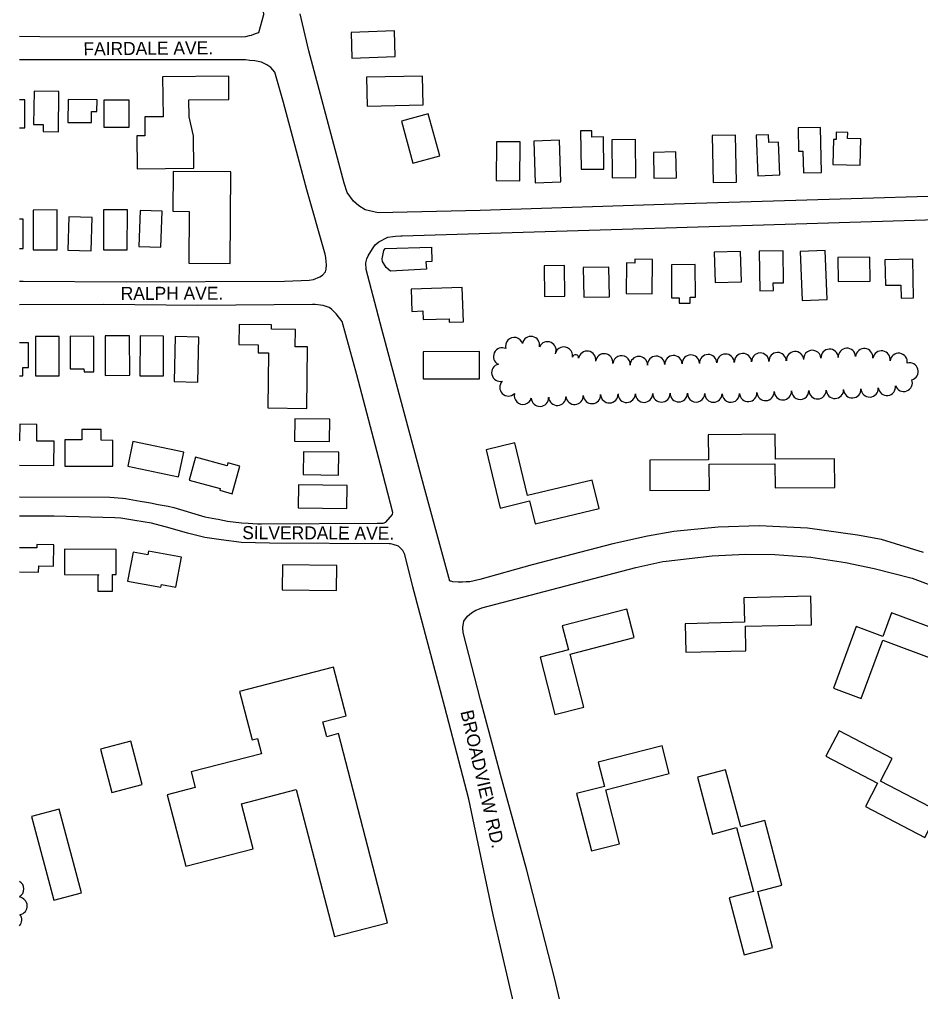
# Model space of a CAD drawing. Extents: x -25029 to 2274964, y -81170 to 687028.
# Drawn here: x -19748 to -18710, y -63741 to -62620 of the extents above; entities that cross this region are included whole.
import ezdxf

# ---------------------------------------------------------------- set-up
doc = ezdxf.new("R2010")
doc.units = 0
for name, color, linetype in [('BLDG', 7, 'Continuous'), ('ROAD', 7, 'Continuous'), ('ROAD-NAME', 7, 'Continuous'), ('TREES', 7, 'Continuous')]:
    doc.layers.add(name, color=color, linetype=linetype)

msp = doc.modelspace()

# ---------------------------------------------------------------- linework, layer by layer
at = {"layer": 'BLDG'}
for points in [[(-19366.4, -62635.5), (-19365.3, -62665.1), (-19315.4, -62663.3), (-19316.4, -62633.7)], [(-19604.1, -62732.9), (-19603.9, -62754.7), (-19613, -62754.8), (-19612.6, -62792.5), (-19547.3, -62791.8), (-19547.7, -62754.6), (-19552.9, -62732.7), (-19553.1, -62713.1), (-19507, -62712.6), (-19507.2, -62685.7), (-19583.4, -62686.5), (-19582.9, -62732.7)], [(-19283.2, -62718.8), (-19284, -62685.7), (-19348.5, -62687.2), (-19347.7, -62720.3)], [(-19732, -62741.6), (-19721, -62741.7), (-19721.1, -62749.8), (-19703.4, -62750), (-19703, -62703.4), (-19731.6, -62703.1)], [(-19692.5, -62739.2), (-19665.5, -62739.3), (-19665.4, -62726.6), (-19659.1, -62726.6), (-19659, -62713), (-19692.4, -62712.8)], [(-19651.1, -62744.7), (-19622.1, -62744.7), (-19622, -62713.6), (-19651, -62713.5)], [(-19308.4, -62737.8), (-19295.1, -62786.3), (-19264.1, -62777.7), (-19277.4, -62729.3)], [(-19075.7, -62755.9), (-19088.9, -62756.1), (-19089, -62748.7), (-19102, -62748.8), (-19101.4, -62793.2), (-19075.3, -62792.9)], [(-18851.3, -62745.6), (-18850.7, -62772.5), (-18845.8, -62772.4), (-18845.3, -62797.3), (-18824.5, -62796.9), (-18825.6, -62745.1)], [(-19126.2, -62759.8), (-19155.7, -62760.8), (-19154.2, -62808.7), (-19124.6, -62807.8)], [(-19065.4, -62803.1), (-19038.2, -62802.7), (-19038.7, -62758.8), (-19065.9, -62759.1)], [(-18923.5, -62753.7), (-18950.2, -62754.3), (-18949, -62808.5), (-18922.3, -62807.9)], [(-18874, -62761.8), (-18885, -62762.3), (-18885.4, -62753.4), (-18899.6, -62754), (-18897.6, -62800.7), (-18872.4, -62799.6)], [(-18778.9, -62758.2), (-18794.4, -62757.7), (-18794.2, -62750.8), (-18807.3, -62750.4), (-18807.5, -62758.8), (-18810.4, -62758.7), (-18811.3, -62787.5), (-18779.8, -62788.4)], [(-19171.6, -62761.7), (-19198.7, -62761.5), (-19199, -62806.3), (-19172, -62806.5)], [(-18992.1, -62773.2), (-19018, -62773.8), (-19017.4, -62803.5), (-18991.4, -62803)], [(-19571.4, -62795.6), (-19571.7, -62841.5), (-19552.9, -62841.7), (-19553.3, -62901.5), (-19505.7, -62901.9), (-19504.9, -62796.1)], [(-19705.1, -62840.1), (-19732.5, -62840.2), (-19732.4, -62886.1), (-19705.1, -62886)], [(-19692.6, -62886.3), (-19665.7, -62887.1), (-19664.5, -62848.9), (-19691.4, -62848.1)], [(-19651.7, -62886), (-19624.2, -62886.1), (-19623.9, -62840.1), (-19651.5, -62840)], [(-19610.9, -62882.1), (-19585.4, -62883), (-19584, -62841.6), (-19609.4, -62840.7)], [(-19279.6, -62908.4), (-19320.8, -62910.7), (-19325.9, -62906.4), (-19330.3, -62899.5), (-19330.5, -62896.4), (-19328.5, -62886.9), (-19327.2, -62884.5), (-19273.7, -62882.8), (-19273.3, -62899.4), (-19280.3, -62899.8)], [(-18946.9, -62923.7), (-18916.6, -62922.8), (-18917.6, -62887.9), (-18947.9, -62888.7)], [(-18895.5, -62933.1), (-18879.8, -62932.9), (-18879.9, -62924.2), (-18868, -62924.1), (-18868.5, -62887.3), (-18896.1, -62887.7)], [(-18846.8, -62944.3), (-18817.7, -62943.1), (-18820, -62886.7), (-18849.1, -62887.9)], [(-18805, -62922.6), (-18768.3, -62922.2), (-18768.7, -62894.3), (-18805.4, -62894.8)], [(-19120.6, -62904.2), (-19144, -62904.5), (-19143.5, -62939.7), (-19120.1, -62939.3)], [(-19069.5, -62905.9), (-19098.9, -62906.5), (-19098.2, -62940.7), (-19068.8, -62940.1)], [(-19019, -62897), (-19039.5, -62896.7), (-19039.5, -62901.3), (-19048.9, -62901.1), (-19049.4, -62936.2), (-19019.6, -62936.6)], [(-18997, -62941.5), (-18988.4, -62941.5), (-18988.4, -62947.5), (-18975.6, -62947.5), (-18975.6, -62940.5), (-18969.6, -62940.5), (-18969.8, -62903), (-18997.2, -62903.2)], [(-18750.8, -62926.9), (-18732.8, -62926.6), (-18732.5, -62941.6), (-18718.5, -62941.3), (-18719.3, -62896.8), (-18751.4, -62897.4)], [(-19297, -62931.2), (-19296.2, -62956.9), (-19283.8, -62956.5), (-19283.4, -62966.5), (-19253.4, -62965.6), (-19253.3, -62969.5), (-19236.9, -62969), (-19238.2, -62929.4)], [(-19417.3, -63068.8), (-19416.4, -62997.9), (-19430.7, -62997.7), (-19430.4, -62977.8), (-19458.1, -62977.4), (-19458, -62972.5), (-19495.1, -62972), (-19495.5, -62995.3), (-19473.2, -62995.6), (-19473.3, -63004.6), (-19461.3, -63004.7), (-19462.2, -63068.2)], [(-19621.3, -63030.5), (-19621.5, -62985.2), (-19649.8, -62985.3), (-19649.5, -63030.7)], [(-19582.3, -62985.4), (-19609.4, -62985.2), (-19609.6, -63031.1), (-19582.5, -63031.2)], [(-19730, -63031.2), (-19702.7, -63031.3), (-19702.6, -62985.8), (-19730, -62985.8)], [(-19689.9, -63023.2), (-19674.3, -63023.2), (-19673.7, -63026.6), (-19662.6, -63026.6), (-19662.5, -62985.8), (-19689.8, -62985.7)], [(-19570.3, -63037.8), (-19542.9, -63038.5), (-19541.7, -62986.5), (-19569.1, -62985.9)], [(-19283.2, -63034.6), (-19218.2, -63034.5), (-19218.3, -63003.2), (-19283.2, -63003.4)], [(-19431.6, -63106.6), (-19391.2, -63107.1), (-19390.9, -63081.1), (-19431.3, -63080.6)], [(-19640.6, -63105.6), (-19654.4, -63105.5), (-19654.4, -63093.1), (-19676.4, -63093), (-19676.5, -63105), (-19696, -63105), (-19696.1, -63135.2), (-19640.7, -63135.3)], [(-19623.6, -63135.4), (-19565.1, -63147.6), (-19559.1, -63119.1), (-19617.6, -63106.8)], [(-19088.6, -63151.4), (-19163, -63169.2), (-19177.5, -63108.5), (-19210.7, -63116.5), (-19194.6, -63183.6), (-19160.7, -63175.4), (-19154.3, -63201.9), (-19080.7, -63184.3)], [(-18809.4, -63126.7), (-18877.5, -63127.2), (-18877.7, -63098.6), (-18954.8, -63099.1), (-18954.5, -63128.1), (-19022.3, -63128.6), (-19022, -63163.4), (-18953.5, -63162.9), (-18953.7, -63133.2), (-18878.1, -63132.6), (-18877.9, -63160.4), (-18809.2, -63159.9)], [(-19421.5, -63145), (-19381, -63145.6), (-19380.6, -63119.3), (-19421.2, -63118.7)], [(-19552.8, -63151.3), (-19517.1, -63161.1), (-19517.7, -63163.1), (-19503.2, -63167.1), (-19494.4, -63135.2), (-19508.2, -63131.4), (-19509.1, -63134.8), (-19545.5, -63124.8)], [(-19427.1, -63183.3), (-19371.1, -63184.1), (-19370.7, -63157.8), (-19426.7, -63157)], [(-19658, -63260.8), (-19658.1, -63279.3), (-19641.1, -63279.4), (-19641, -63260), (-19637, -63260), (-19636.8, -63231.2), (-19696.3, -63230.9), (-19696.5, -63260.3), (-19657.1, -63260.6)], [(-19561.7, -63240.2), (-19599.7, -63233.2), (-19600.5, -63237.5), (-19617.5, -63234.4), (-19623.7, -63267.8), (-19585.3, -63274.9), (-19584.7, -63271.8), (-19568.1, -63274.9)], [(-19445.8, -63277.8), (-19383, -63278.6), (-19382.7, -63249.7), (-19445.4, -63248.9)], [(-18913.2, -63315.3), (-18981.5, -63317), (-18980.7, -63349.7), (-18911.4, -63348.1), (-18912.1, -63319.9), (-18836, -63318.1), (-18836.8, -63285.1), (-18913.8, -63287)], [(-19115.9, -63346.9), (-19148.6, -63355.3), (-19131.4, -63421.7), (-19098.2, -63413.1), (-19114, -63351.9), (-19040.3, -63332.9), (-19048.7, -63300.3), (-19123, -63319.5)], [(-18753.9, -63331.5), (-18784.3, -63320.2), (-18810.7, -63391.3), (-18778.6, -63403.2), (-18753.7, -63336), (-18691.2, -63359.2), (-18679.7, -63328.1), (-18743.8, -63304.3)], [(-19480.2, -63450.8), (-19474.3, -63449.3), (-19469.7, -63466.9), (-19550.5, -63487.8), (-19545.9, -63505.8), (-19578, -63514.1), (-19556.7, -63596.4), (-19479, -63576.2), (-19492.4, -63524.4), (-19429.4, -63508.1), (-19385.5, -63677.4), (-19324.3, -63661.5), (-19380.8, -63443.6), (-19394.3, -63447.1), (-19398.8, -63429.9), (-19372.1, -63423), (-19386.7, -63366.9), (-19494.7, -63394.9)], [(-18616, -63540.5), (-18677.3, -63508.5), (-18690, -63532.9), (-18756.4, -63498.2), (-18742.8, -63472.2), (-18803.9, -63440.2), (-18819.3, -63469.7), (-18759.7, -63500.8), (-18773.6, -63527.4), (-18705.4, -63563.1), (-18692.6, -63538.6), (-18631.7, -63570.5)], [(-19654.9, -63461.5), (-19641.9, -63511.4), (-19606.9, -63502.3), (-19619.9, -63452.4)], [(-19074.5, -63504.4), (-19106.5, -63512.7), (-19089.5, -63578.8), (-19057, -63570.5), (-19073, -63508.3), (-18999.9, -63489.5), (-19008.1, -63457.7), (-19081.6, -63476.6)], [(-18922.2, -63551.9), (-18902.8, -63625.4), (-18930.8, -63632.8), (-18913.4, -63698.7), (-18880.7, -63690.1), (-18897.8, -63625.4), (-18870.1, -63618.1), (-18889.8, -63543.8), (-18917.5, -63551.1), (-18934.9, -63485.2), (-18967.4, -63493.8), (-18950.1, -63559.3)], [(-19677, -63627), (-19702.5, -63530.5), (-19734.5, -63538.9), (-19708.9, -63635.4)]]:
    msp.add_lwpolyline(points, close=True, dxfattribs=at)
for points in [[(-19748.4, -62745.6), (-19742.3, -62745.6), (-19742.2, -62713), (-19748.4, -62713)], [(-19748.4, -62884.3), (-19744.1, -62884.3), (-19744.2, -62850.6), (-19748.4, -62850.7)], [(-19748.4, -63031.1), (-19744.5, -63031.1), (-19744.5, -63021.5), (-19738, -63021.5), (-19738.1, -62993.3), (-19748.4, -62993.3)], [(-19708.5, -63106.7), (-19728.5, -63106.4), (-19728.2, -63087.2), (-19748.1, -63086.9), (-19748.4, -63106), (-19748.4, -63106)], [(-19748.4, -63134.2), (-19708.9, -63134.7), (-19708.5, -63106.7)], [(-19726.2, -63250.1), (-19709.1, -63250.4), (-19708.7, -63226.1), (-19728.3, -63225.7), (-19728.3, -63229.6), (-19748.4, -63229.3)], [(-19748.4, -63257), (-19726.3, -63257.4), (-19726.2, -63250.1)]]:
    msp.add_lwpolyline(points, dxfattribs=at)
at = {"layer": 'ROAD'}
for points in [[(-19748.4, -62301.3), (-19501, -62301), (-19496.1, -62301.8), (-19489.8, -62305), (-19487.7, -62306.7), (-19481.6, -62314.6), (-19480.5, -62320.9), (-19480.1, -62324.7), (-19479.9, -62329.9), (-19477.6, -62493.8), (-19476.9, -62533.7), (-19475.6, -62546.3), (-19474.2, -62562.9), (-19470.1, -62593.3), (-19468.4, -62601.7), (-19467.3, -62615.1), (-19472.9, -62636), (-19477, -62637.2), (-19481.5, -62639), (-19483.9, -62639.5), (-19488, -62640.4), (-19493, -62641.1), (-19725, -62640.4), (-19748.4, -62640.3)], [(-17885.8, -62799.6), (-18017.9, -62804.1), (-18202.6, -62809.4), (-18416.9, -62815.9), (-18613.6, -62821.9), (-18764.3, -62826.6), (-18982.3, -62833.1), (-19217.5, -62840.6), (-19335.1, -62843.5), (-19349.9, -62839.8), (-19357.5, -62835.4), (-19363.7, -62829.8), (-19370.7, -62820), (-19374.1, -62809.3), (-19414.9, -62656.6), (-19424.8, -62613.9)], [(-19748.4, -62922.1), (-19744.1, -62922.1), (-19625.3, -62922.9), (-19443, -62922.2), (-19423.7, -62921.2), (-19414.7, -62921.1), (-19409.8, -62920.4), (-19402.2, -62917.1), (-19399.1, -62915.2), (-19395.7, -62911.3), (-19395.2, -62908.3), (-19394.8, -62903.2), (-19395.2, -62899.6), (-19395.5, -62894.9), (-19396.2, -62891.2), (-19417.1, -62817), (-19444.1, -62716.4), (-19454.2, -62681.2), (-19458.8, -62675.7), (-19463.2, -62672.8), (-19469.7, -62669.9), (-19477.1, -62668.3), (-19482.9, -62667.7), (-19487.9, -62667.1), (-19623.8, -62667.1), (-19744.7, -62667), (-19748.4, -62667)], [(-19349.2, -62901), (-19348, -62896.4), (-19346.5, -62893), (-19341.8, -62884.9), (-19338.5, -62880.2), (-19334.5, -62876.8), (-19323.9, -62871.6), (-19318.2, -62870.5), (-19315.1, -62870.1), (-19308.9, -62869.8), (-19307.3, -62869.7), (-19066.5, -62862.7), (-18866.2, -62856.4), (-18654.5, -62849.8), (-18462, -62844.4), (-18216.5, -62836.7), (-18000.8, -62829.7), (-17884.9, -62826.1)], [(-18706.8, -63234.7), (-18755.4, -63219.8), (-18782.9, -63214.8), (-18840.4, -63206.9), (-18896.1, -63204.2), (-18943.4, -63205.8), (-18994.4, -63210.6), (-19024.8, -63216), (-19064.9, -63224.7), (-19157.7, -63249.1), (-19217.8, -63266), (-19229.6, -63268.5), (-19233.7, -63268.8), (-19238.1, -63269.2), (-19243.1, -63269.1), (-19249.2, -63268.5), (-19251.2, -63268), (-19252.7, -63267.8), (-19282.6, -63157.9), (-19330.7, -62977.5), (-19349.1, -62908.6), (-19349.2, -62901)], [(-19748.4, -63170.5), (-19644.4, -63171.1), (-19629.7, -63172.2), (-19626.1, -63172.7), (-19609.4, -63175.7), (-19602.1, -63176.8), (-19597.4, -63177.6), (-19588.4, -63179.5), (-19576.9, -63181.3), (-19570.7, -63183.1), (-19534.7, -63193.6), (-19522.2, -63196.2), (-19519.4, -63196.5), (-19508.7, -63198.6), (-19492.6, -63200.6), (-19484.9, -63201.2), (-19474.3, -63201.8), (-19469.5, -63201.9), (-19336.1, -63201.2), (-19329.2, -63201.1), (-19326.4, -63199.7), (-19318.6, -63191.1), (-19318.2, -63188.9), (-19318.3, -63188.6), (-19332.3, -63133.7), (-19359.8, -63030.1), (-19376.7, -62968.7), (-19383.5, -62959.7), (-19388.9, -62954.3), (-19391.5, -62952.6), (-19398.6, -62950.1), (-19407.6, -62949), (-19410.9, -62949), (-19543.2, -62950), (-19651.5, -62949), (-19748.4, -62949.4)], [(-19084.3, -64157.9), (-19183.3, -63735.5), (-19202.6, -63652.3), (-19230.5, -63519), (-19258.4, -63413.1), (-19295.2, -63274.3), (-19304.5, -63237), (-19306.7, -63232.4), (-19311.5, -63227.7), (-19317.7, -63225.5), (-19320.9, -63224.9), (-19322.5, -63224.7), (-19460.3, -63223.9), (-19492.4, -63223.2), (-19516, -63220.3), (-19534.9, -63217.4), (-19554.7, -63212.4), (-19574.9, -63206.7), (-19596.2, -63201.2), (-19615.5, -63197.9), (-19631.6, -63195.3), (-19638.3, -63195), (-19708.3, -63193.1), (-19748.4, -63193.1)], [(-19104.1, -63844.3), (-19132, -63724.9), (-19163.7, -63600.9), (-19194.3, -63490.8), (-19217.1, -63404.7), (-19237.1, -63327.2), (-19237.6, -63321.3), (-19236.5, -63314), (-19232.1, -63308.3), (-19227.4, -63304.5), (-19222.6, -63301.4), (-19218.5, -63299.7), (-19215.5, -63298.6), (-19038.2, -63252.3), (-19007.3, -63245.2), (-19003.2, -63244.7), (-18950.4, -63238.6), (-18911.9, -63236.8), (-18878, -63237.3), (-18836.7, -63240.2), (-18796.8, -63246.4), (-18763.8, -63253.1), (-18720, -63264.5), (-18675.7, -63280.8)]]:
    msp.add_lwpolyline(points, dxfattribs=at)
at = {"layer": 'TREES'}
for centre, radius, start, end in [((-19178.4, -62996.9), 10, 17.27, 197.27), ((-19159.1, -62995.8), 10, 348.8905, 168.8905), ((-19140.1, -63001.9), 10, 335.6223, 155.6223), ((-19192.3, -63008.9), 10, 64.4508, 244.4508), ((-19121.2, -63007.9), 10, 349.2079, 169.2079), ((-19107.8, -63010.4), 3.61, 350.0072, 170.0072), ((-19094.4, -63012.7), 10, 350.3824, 170.3824), ((-19074.7, -63015.7), 10, 352.2579, 172.2579), ((-18994.9, -63017.8), 10, 2.071, 182.071), ((-18974.9, -63017.1), 10, 1.6439, 181.6439), ((-18954.9, -63016.6), 10, 1.3434, 181.3434), ((-18934.9, -63016.1), 10, 1.6439, 181.6439), ((-18914.9, -63015.5), 10, 1.7258, 181.7258), ((-18894.9, -63014.9), 10, 1.6126, 181.6126), ((-18874.9, -63014.3), 10, 2.0485, 182.0485), ((-18854.9, -63013.2), 10, 3.9777, 183.9777), ((-18835, -63011.7), 10, 4.741, 184.741), ((-18815, -63010.4), 10, 2.5631, 182.5631), ((-18795.1, -63009.4), 10, 3.0307, 183.0307), ((-18775.1, -63009.8), 10, 354.5684, 174.5684), ((-18755.3, -63012.4), 10, 350.9283, 170.9283), ((-18735.5, -63015.2), 10, 352.8451, 172.8451), ((-19194.4, -63027.6), 10, 102.8114, 282.8114), ((-19054.8, -63018), 10, 354.5903, 174.5903), ((-19034.8, -63018.9), 10, 0.3989, 180.3989), ((-19014.8, -63018.5), 10, 1.9359, 181.9359), ((-18723, -63026.1), 10, 285.0312, 105.0312), ((-19185.1, -63044.5), 10, 135.0302, 315.0302), ((-18729.7, -63039.3), 10, 200.5404, 20.5404), ((-19168.4, -63054.1), 10, 164.8847, 344.8847), ((-19068.8, -63052.5), 10, 181.8887, 1.8887), ((-19048.8, -63052), 10, 180.8203, 0.8203), ((-19028.8, -63051.8), 10, 180.6072, 0.6072), ((-19008.8, -63051.5), 10, 181.0944, 1.0944), ((-18988.8, -63051.3), 10, 179.9045, 359.9045), ((-18968.8, -63051.5), 10, 179.247, 359.247), ((-18948.8, -63051.7), 10, 179.2682, 359.2682), ((-18928.8, -63051.7), 10, 181.0658, 1.0658), ((-18908.8, -63050.9), 10, 183.3814, 3.3814), ((-18888.9, -63049.8), 10, 182.9051, 2.9051), ((-18868.9, -63049), 10, 181.8427, 1.8427), ((-18848.9, -63048.4), 10, 181.5103, 1.5103), ((-18828.9, -63047.9), 10, 181.4158, 1.4158), ((-18808.9, -63047.4), 10, 181.3054, 1.3054), ((-18788.9, -63046.7), 10, 182.8028, 2.8028), ((-18769, -63045.7), 10, 182.8822, 2.8822), ((-18749, -63044), 10, 186.9562, 6.9562), ((-19148.7, -63056.4), 10, 182.1945, 2.1945), ((-19128.7, -63055.4), 10, 183.107, 3.107), ((-19108.8, -63054.3), 10, 183.2643, 3.2643), ((-19088.8, -63053.3), 10, 182.5647, 2.5647), ((-19753.2, -63622.6), 10, 299.0875, 60.9125), ((-19749.3, -63642.2), 10, 279.2684, 84.5942), ((-19755.7, -63658.1), 10, 316.8035, 37.2634)]:
    msp.add_arc(centre, radius, start, end, dxfattribs=at)

# ---------------------------------------------------------------- texts
at = {"layer": 'ROAD-NAME'}
for s, height, rotation, p in [('FAIRDALE AVE.', 15, 0.4964, (-19674.6, -62661.9)), ('RALPH AVE.', 14.99, 0.0671, (-19631.7, -62943.7)), ('SILVERDALE AVE.', 15, 359.7656, (-19491.7, -63219.4)), ('BROADVIEW RD.', 14.99, 283.0933, (-19240.5, -63418.3))]:
    msp.add_text(s, height=height, rotation=rotation, dxfattribs=at).set_placement(p)

doc.saveas('drawing.dxf')
